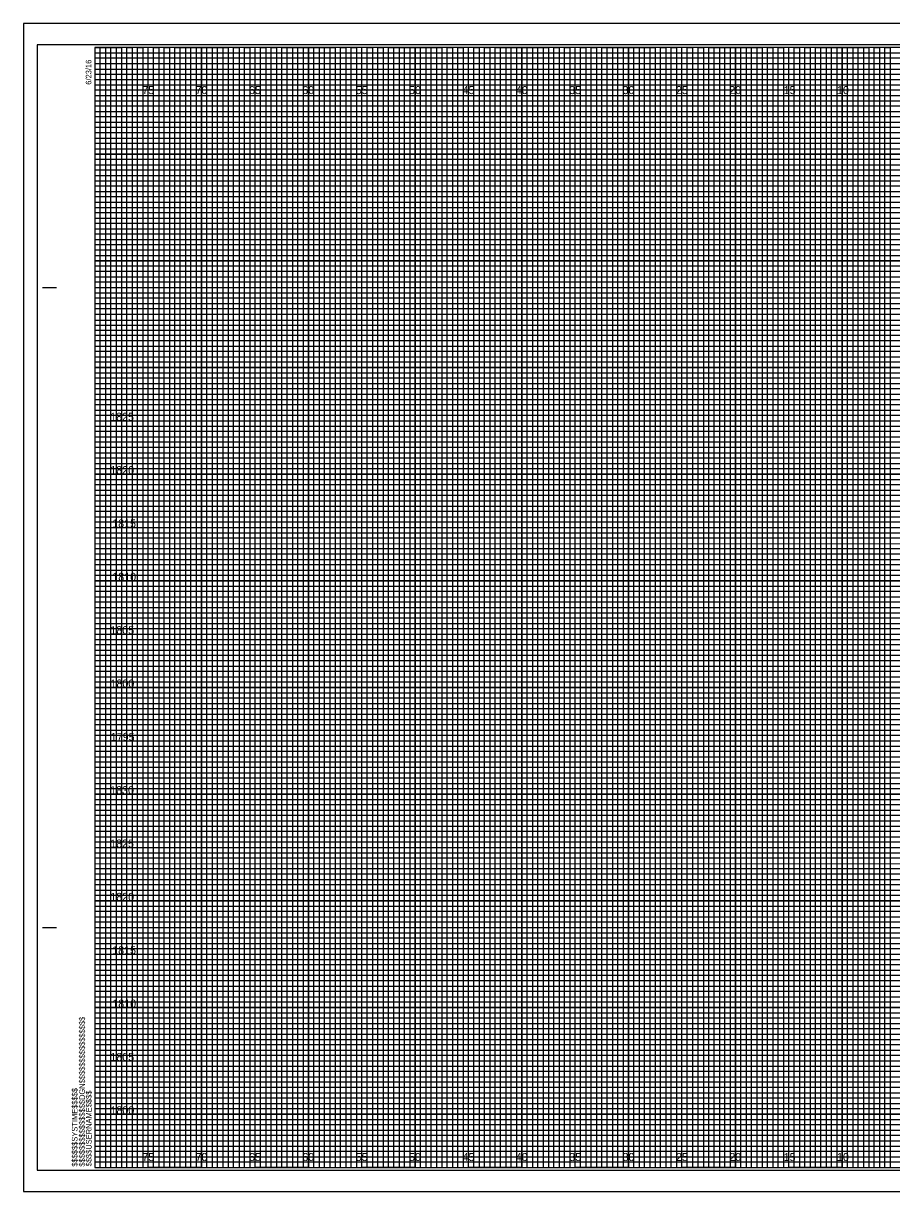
# Model space of a CAD drawing. Extents: x -7 to 162, y -2 to 767.
# Drawn here: x -6.7 to 74.6, y 217.7 to 327.2 of the extents above; entities that cross this region are included whole.
import ezdxf

# ---------------------------------------------------------------- set-up
doc = ezdxf.new("R2010")
doc.units = 0
for name, color, linetype in [('Prop Grid Mask', 7, 'Continuous'), ('Prop XS Elevation Labels', 7, 'Continuous'), ('Sheet Cross Section CELL', 7, 'Continuous'), ('Sheet Cross Section Grid Major CELL', 7, 'Continuous'), ('Sheet Cross Section Grid Middle CELL', 7, 'Continuous'), ('Sheet Cross Section Grid Minor 1 CELL', 7, 'Continuous'), ('Sheet Cross Section Grid Minor 2 CELL', 7, 'Continuous'), ('Sheet Cutting Line CELL', 7, 'Continuous'), ('Sheet DOT Grid CELL', 7, 'Continuous'), ('Sheet Plot Border Inside CELL', 7, 'Continuous'), ('Sheet Plot Border Outside CELL', 7, 'Continuous')]:
    doc.layers.add(name, color=color, linetype=linetype)

msp = doc.modelspace()

# ---------------------------------------------------------------- linework, layer by layer
at = {"layer": 'Sheet Cross Section CELL'}
for p, q in [((-4.9, 302.5), (-3.65, 302.5)), ((-4.85, 302.5), (-3.6, 302.5)), ((-4.9, 242.5), (-3.65, 242.5)), ((-4.85, 242.5), (-3.6, 242.5)), ((0, 220), (0, 220)), ((0, 220), (0, 220)), ((0, 220), (0, 220)), ((0, 220), (0, 220)), ((0, 220), (0, 220)), ((0, 220), (0, 220)), ((0, 220), (0, 220))]:
    msp.add_line(p, q, dxfattribs=at)
msp.add_lwpolyline([(160, 325), (0, 325), (0, 220), (160, 220)], close=True, dxfattribs=at)
at = {"layer": 'Sheet Cross Section Grid Major CELL'}
for p, q in [((5, 325), (0, 325)), ((5, 220), (5, 325)), ((15, 325), (10, 325)), ((10, 325), (10, 220)), ((15, 220), (15, 325)), ((25, 325), (20, 325)), ((20, 325), (20, 220)), ((25, 220), (25, 325)), ((35, 325), (30, 325)), ((30, 325), (30, 220)), ((35, 220), (35, 325)), ((45, 325), (40, 325)), ((40, 325), (40, 220)), ((45, 220), (45, 325)), ((55, 325), (50, 325)), ((50, 325), (50, 220)), ((55, 220), (55, 325)), ((65, 325), (60, 325)), ((60, 325), (60, 220)), ((65, 220), (65, 325)), ((75, 325), (70, 325)), ((70, 325), (70, 220)), ((10, 220), (5, 220)), ((20, 220), (15, 220)), ((30, 220), (25, 220)), ((40, 220), (35, 220)), ((50, 220), (45, 220)), ((60, 220), (55, 220)), ((70, 220), (65, 220))]:
    msp.add_line(p, q, dxfattribs=at)
for points in [[(0, 320), (160, 320), (160, 315), (0, 315)], [(0, 310), (160, 310), (160, 305), (0, 305)], [(0, 300), (160, 300), (160, 295), (0, 295)], [(0, 290), (160, 290), (160, 285), (0, 285)], [(0, 280), (160, 280), (160, 275), (0, 275)], [(0, 270), (160, 270), (160, 265), (0, 265)], [(0, 260), (160, 260), (160, 255), (0, 255)], [(0, 250), (160, 250), (160, 245), (0, 245)], [(0, 240), (160, 240), (160, 235), (0, 235)], [(0, 230), (160, 230), (160, 225), (0, 225)]]:
    msp.add_lwpolyline(points, dxfattribs=at)
at = {"layer": 'Sheet Cross Section Grid Middle CELL'}
for points in [[(0, 325), (2.5, 325), (2.5, 220), (7.5, 220), (7.5, 325), (12.5, 325), (12.5, 220), (17.5, 220), (17.5, 325), (22.5, 325), (22.5, 220), (27.5, 220), (27.5, 325), (32.5, 325), (32.5, 220), (37.5, 220), (37.5, 325), (42.5, 325), (42.5, 220), (47.5, 220), (47.5, 325), (52.5, 325), (52.5, 220), (57.5, 220), (57.5, 325), (62.5, 325), (62.5, 220), (67.5, 220), (67.5, 325), (72.5, 325), (72.5, 220), (77.5, 220)], [(0, 322.5), (137.5, 322.5)], [(0, 312.5), (160, 312.5), (160, 317.5), (0, 317.5)], [(0, 302.5), (160, 302.5), (160, 307.5), (0, 307.5)], [(0, 292.5), (160, 292.5), (160, 297.5), (0, 297.5)], [(0, 282.5), (160, 282.5), (160, 287.5), (0, 287.5)], [(0, 272.5), (160, 272.5), (160, 277.5), (0, 277.5)], [(0, 262.5), (160, 262.5), (160, 267.5), (0, 267.5)], [(0, 252.5), (160, 252.5), (160, 257.5), (0, 257.5)], [(0, 242.5), (160, 242.5), (160, 247.5), (0, 247.5)], [(0, 232.5), (160, 232.5), (160, 237.5), (0, 237.5)], [(0, 222.5), (160, 222.5), (160, 227.5), (0, 227.5)]]:
    msp.add_lwpolyline(points, dxfattribs=at)
at = {"layer": 'Sheet Cross Section Grid Minor 1 CELL'}
for p, q in [((0, 324.5), (130, 324.5)), ((130, 323.99), (0, 323.99)), ((0, 323.99), (0, 323.5)), ((0, 323.5), (130, 323.5)), ((130, 322.94), (0, 322.94)), ((0, 322.94), (0, 322)), ((0, 322), (160, 322))]:
    msp.add_line(p, q, dxfattribs=at)
for points in [[(0, 321.5), (135, 321.5), (160, 321.5), (160, 321), (0, 321)], [(0, 320.5), (160, 320.5), (160, 319.5), (0, 319.5)], [(0, 319), (160, 319), (160, 318.5), (0, 318.49)], [(0, 318), (160, 318), (160, 317), (0, 317)], [(0, 316.5), (160, 316.5), (160, 316), (0, 316)], [(0, 315.5), (160, 315.5), (160, 314.5), (0, 314.5)], [(0, 314), (160, 314), (160, 313.5), (0, 313.5)], [(0, 313), (160, 313), (160, 312), (0, 312)], [(0, 311.5), (160, 311.5), (160, 311), (0, 311)], [(0, 310.5), (160, 310.5), (160, 309.5), (0, 309.5)], [(0, 309), (160, 309), (160, 308.5), (0, 308.5)], [(0, 308), (160, 308), (160, 306.98), (160, 306.5), (160, 306), (0, 306)], [(0, 307), (160, 307), (160, 306.5), (0, 306.5)], [(0, 305.5), (160, 305.5), (160, 304.5), (0, 304.51)], [(0, 304.51), (160, 304.5), (160, 304), (0, 304)], [(0, 303.5), (160, 303.5), (160, 303), (0, 303)], [(0, 302), (160, 302), (160, 301.5), (0, 301.5)], [(0, 301), (160, 301), (160, 300.5), (0, 300.5)], [(-0.04, 299.44), (160, 299.44), (160, 298.94), (-0.04, 298.94)], [(0, 298.5), (160, 298.5), (160, 298), (0, 298)], [(0, 297), (160, 297), (160, 296.5), (0, 296.5)], [(0, 296), (160, 296), (160, 295.5), (0, 295.5)], [(0, 294.5), (160, 294.5), (160, 294), (0, 294)], [(0, 293.5), (160, 293.5), (160, 293), (0, 293)], [(0, 292), (160, 292), (160, 291.5), (0, 291.5)], [(0, 291), (160, 291), (160, 290.5), (0, 290.5)], [(0, 289.5), (160, 289.5), (160, 288.99), (0, 289)], [(0, 288.5), (160, 288.5), (160, 288), (0, 288)], [(0, 287), (160, 287), (160, 286.5), (0, 286.5)], [(0, 286), (160, 286), (160, 285.5), (0, 285.5)], [(0, 284.5), (160, 284.5), (160, 284), (0, 284)], [(0, 283.5), (160, 283.5), (160, 283), (0, 283)], [(0, 282), (160, 282), (160, 281.5), (0, 281.5)], [(0, 281), (160, 281), (160, 280.5), (0, 280.5)], [(0, 279.5), (160, 279.5), (160, 279), (0, 279)], [(0, 278.5), (160.03, 278.45), (160, 278), (0, 278)], [(0, 277), (160, 277), (160, 276.5), (0, 276.5)], [(0, 276), (160, 276), (160, 275.5), (0, 275.5)], [(0, 274.5), (160, 274.5), (160, 274), (0, 274)], [(0, 273.5), (160, 273.5), (160, 273), (0, 273)], [(0, 272), (160, 272), (160, 271.5), (0, 271.5)], [(0, 271), (160, 271), (160, 270.5), (0, 270.5)], [(0, 269.5), (160, 269.5), (160, 269), (0, 269)], [(0, 268.5), (160, 268.5), (160, 268), (0, 268)], [(0, 267), (160, 267), (160, 266.5), (0, 266.5)], [(0, 266), (160, 266), (160, 265.5), (0, 265.5)], [(0, 264.5), (160, 264.5), (160, 264), (0, 264)], [(0, 263.5), (160, 263.5), (160, 263), (0, 263)], [(0, 262), (160, 262), (160, 261.5), (0, 261.5)], [(0, 261), (160, 261), (160, 260.5), (0, 260.5)], [(0, 259.5), (160, 259.5), (160, 258.99), (0, 259)], [(0, 258.5), (160, 258.5), (160, 258), (0, 258)], [(0, 257), (160, 257), (160, 256.5), (0, 256.5)], [(0, 256), (160, 256), (160, 255.5), (0, 255.5)], [(0, 254.5), (160, 254.5), (160, 254), (0, 254)], [(0, 253.5), (160, 253.5), (160, 253), (0, 253)], [(0, 252), (160, 252), (160, 251.5), (0, 251.5)], [(0, 251), (160, 251), (160, 250.5), (0, 250.5)], [(0, 249.5), (160, 249.5), (160, 249), (0, 249)], [(0, 248.5), (160.03, 248.46), (160, 248), (0, 248)], [(0, 247), (160, 247), (160, 246.5), (0, 246.5)], [(0, 246), (160, 246), (160, 245.5), (0, 245.5)], [(0, 244.5), (160, 244.5), (160, 244), (0, 244)], [(0, 243.5), (160, 243.5), (160, 243), (0, 243)], [(0, 242), (160, 242), (160, 241.5), (0, 241.5)], [(0, 241), (160, 241), (160, 240.5), (0, 240.5)], [(0, 239.5), (160, 239.5), (160, 239), (0, 239)], [(0, 238.5), (160, 238.5), (160, 238), (0, 238)], [(0, 237), (160, 237), (160, 236.5), (0, 236.5)], [(0, 236), (160, 236), (160, 235.5), (0, 235.5)], [(0, 234.5), (160, 234.5), (160, 234), (0, 234)], [(0, 233.5), (160, 233.5), (160, 233), (0, 233)], [(0, 232), (160, 232), (160, 231.5), (0, 231.5)], [(0, 231), (160, 231), (160, 230.5), (0, 230.5)], [(0, 229.5), (160, 229.5), (160, 229), (0, 229)], [(0, 228.5), (160, 228.5), (160, 228), (0, 228)], [(0, 227), (160, 227), (160, 226.5), (0, 226.5)], [(0, 226), (160, 226), (160, 225.5), (0, 225.5)], [(0, 224.5), (160, 224.5), (160, 224), (0, 224)], [(0, 223.5), (160, 223.5), (160, 223), (0, 223)], [(0, 222), (160, 222), (160, 221.5), (0, 221.5)], [(0, 221), (160, 221), (160, 220.5), (0, 220.5)]]:
    msp.add_lwpolyline(points, dxfattribs=at)
at = {"layer": 'Sheet Cross Section Grid Minor 2 CELL'}
for points in [[(0, 220), (0.5, 220), (0.5, 325), (1, 325), (1, 220)], [(1, 220), (1.5, 220), (1.5, 325), (2, 325), (2, 220)], [(2.5, 220), (3, 220), (3, 325), (3.5, 325), (3.5, 220)], [(3.5, 220), (4, 220), (4, 325), (4.5, 325), (4.5, 220)], [(5, 220), (5.5, 220), (5.5, 325), (6, 325), (6, 220)], [(6, 220), (6.5, 220), (6.5, 325), (7, 325), (7, 220)], [(7.5, 220), (8, 220), (8, 325), (8.5, 325), (8.5, 220)], [(8.5, 220), (9, 220), (9, 325), (9.5, 325), (9.5, 220)], [(10, 220), (10.5, 220), (10.5, 325), (11, 325), (11, 220)], [(11, 220), (11.5, 220), (11.5, 325), (12, 325), (12, 220)], [(12.5, 220), (13, 220), (13, 325), (13.5, 325), (13.5, 220)], [(13.5, 220), (14, 220), (14, 325), (14.5, 325), (14.5, 220)], [(15, 220), (15.5, 220), (15.5, 325), (16, 325), (16, 220)], [(16, 220), (16.5, 220), (16.5, 325), (17, 325), (17, 220)], [(17.5, 220), (18, 220), (18, 325), (18.5, 325), (18.5, 220)], [(18.5, 220), (19, 220), (19, 325), (19.5, 325), (19.5, 220)], [(20, 220), (20.5, 220), (20.5, 325), (21, 325), (21, 220)], [(21, 220), (21.5, 220), (21.5, 325), (22, 325), (22, 220)], [(22.5, 220), (23, 220), (23, 325), (23.5, 325), (23.5, 220)], [(23.5, 220), (24, 220), (24, 325), (24.5, 325), (24.5, 220)], [(25, 220), (25.5, 220), (25.5, 325), (26, 325), (26, 220)], [(26, 220), (26.5, 220), (26.5, 325), (27, 325), (27, 220)], [(27.5, 220), (28, 220), (28, 325), (28.5, 325), (28.5, 220)], [(28.5, 220), (29, 220), (29, 325), (29.5, 325), (29.5, 220)], [(30, 220), (30.5, 220), (30.5, 325), (31, 325), (31, 220)], [(31, 220), (31.5, 220), (31.5, 325), (32, 325), (32, 220)], [(32.5, 220), (33, 220), (33, 325), (33.5, 325), (33.5, 220)], [(33.5, 220), (34, 220), (34, 325), (34.5, 325), (34.5, 220)], [(35, 220), (35.5, 220), (35.5, 325), (36, 325), (36, 220)], [(36, 220), (36.5, 220), (36.5, 325), (37, 325), (37, 220)], [(37.5, 220), (38, 220), (38, 325), (38.5, 325), (38.5, 220)], [(38.5, 220), (39, 220), (39, 325), (39.5, 325), (39.5, 220)], [(40, 220), (40.5, 220), (40.5, 325), (41, 325), (41, 220)], [(41, 220), (41.5, 220), (41.5, 325), (42, 325), (42, 220)], [(42.5, 220), (43, 220), (43, 325), (43.5, 325), (43.5, 220)], [(43.5, 220), (44, 220), (44, 325), (44.5, 325), (44.5, 220)], [(45, 220), (45.5, 220), (45.5, 325), (46, 325), (46, 220)], [(46, 220), (46.5, 220), (46.5, 325), (47, 325), (47, 220)], [(47.5, 220), (48, 220), (48, 325), (48.5, 325), (48.5, 220)], [(48.5, 220), (49, 220), (49, 325), (49.5, 325), (49.5, 220)], [(50, 220), (50.5, 220), (50.5, 325), (51, 325), (51, 220)], [(51, 220), (51.5, 220), (51.5, 325), (52, 325), (52, 220)], [(52.5, 220), (53, 220), (53, 325), (53.5, 325), (53.5, 220)], [(53.5, 220), (54, 220), (54, 325), (54.5, 325), (54.5, 220)], [(55, 220), (55.5, 220), (55.5, 325), (56, 325), (56, 220)], [(56, 220), (56.5, 220), (56.5, 325), (57, 325), (57, 220)], [(57.5, 220), (58, 220), (58, 325), (58.5, 325), (58.5, 220)], [(58.5, 220), (59, 220), (59, 325), (59.5, 325), (59.5, 220)], [(60, 220), (60.5, 220), (60.5, 325), (61, 325), (61, 220)], [(61, 220), (61.5, 220), (61.5, 325), (62, 325), (62, 220)], [(62.5, 220), (63, 220), (63, 325), (63.5, 325), (63.5, 220)], [(63.5, 220), (64, 220), (64, 325), (64.5, 325), (64.5, 220)], [(65, 220), (65.5, 220), (65.5, 325), (66, 325), (66, 220)], [(66, 220), (66.5, 220), (66.5, 325), (67, 325), (67, 220)], [(67.5, 220), (68, 220), (68, 325), (68.5, 325), (68.5, 220)], [(68.5, 220), (69, 220), (69, 325), (69.5, 325), (69.5, 220)], [(70, 220), (70.5, 220), (70.5, 325), (71, 325), (71, 220)], [(71, 220), (71.5, 220), (71.5, 325), (72, 325), (72, 220)], [(72.5, 220), (73, 220), (73, 325), (73.5, 325), (73.5, 220)], [(73.5, 220), (74, 220), (74, 325), (74.5, 325), (74.5, 220)]]:
    msp.add_lwpolyline(points, dxfattribs=at)
at = {"layer": 'Sheet Cutting Line CELL'}
for p, q in [((161.65, 327.25), (-6.7, 327.25)), ((-6.7, 327.25), (-6.7, 217.75)), ((-6.7, 217.75), (161.65, 217.75))]:
    msp.add_line(p, q, dxfattribs=at)
at = {"layer": 'Sheet DOT Grid CELL'}
for p, q in [((5, 220), (5, 325)), ((10, 220), (10, 325)), ((15, 220), (15, 325)), ((20, 220), (20, 325)), ((25, 220), (25, 325)), ((30, 220), (30, 325)), ((35, 220), (35, 325)), ((40, 220), (40, 325)), ((45, 220), (45, 325)), ((50, 220), (50, 325)), ((55, 220), (55, 325)), ((60, 220), (60, 325)), ((65, 220), (65, 325)), ((70, 220), (70, 325)), ((0, 320), (160, 320)), ((0, 315), (160, 315)), ((0, 310), (160, 310)), ((0, 305), (160, 305)), ((0, 300), (160, 300)), ((0, 295), (160, 295)), ((0, 290), (160, 290)), ((0, 285), (160, 285)), ((0, 280), (160, 280)), ((0, 275), (160, 275)), ((0, 270), (160, 270)), ((0, 265), (160, 265)), ((0, 260), (160, 260)), ((0, 255), (160, 255)), ((0, 250), (160, 250)), ((0, 245), (160, 245)), ((0, 240), (160, 240)), ((0, 235), (160, 235)), ((0, 230), (160, 230)), ((0, 225), (160, 225))]:
    msp.add_line(p, q, dxfattribs=at)
at = {"layer": 'Sheet Plot Border Inside CELL'}
msp.add_lwpolyline([(-5.4, 219.75), (161.2, 219.75), (161.2, 325.25), (-5.4, 325.25)], close=True, dxfattribs=at)
at = {"layer": 'Sheet Plot Border Outside CELL'}
msp.add_lwpolyline([(-6.7, 217.75), (161.65, 217.75), (161.65, 327.25), (-6.7, 327.25)], close=True, dxfattribs=at)

# ---------------------------------------------------------------- texts
at = {"layer": 'Prop Grid Mask'}
for s, p in [('75', (4.44, 320.62)), ('70', (9.43, 320.62)), ('65', (14.44, 320.62)), ('60', (19.43, 320.62)), ('55', (24.44, 320.62)), ('50', (29.43, 320.62)), ('45', (34.44, 320.62)), ('40', (39.43, 320.62)), ('35', (44.44, 320.62)), ('30', (49.43, 320.62)), ('25', (54.44, 320.62)), ('20', (59.43, 320.62)), ('15', (64.53, 320.62)), ('10', (69.52, 320.62)), ('75', (4.44, 220.62)), ('70', (9.43, 220.62)), ('65', (14.44, 220.62)), ('60', (19.43, 220.62)), ('55', (24.44, 220.62)), ('50', (29.43, 220.62)), ('45', (34.44, 220.62)), ('40', (39.43, 220.62)), ('35', (44.44, 220.62)), ('30', (49.43, 220.62)), ('25', (54.44, 220.62)), ('20', (59.43, 220.62)), ('15', (64.53, 220.62)), ('10', (69.52, 220.62))]:
    msp.add_text(s, height=0.75, dxfattribs=at).set_placement(p)
at = {"layer": 'Prop XS Elevation Labels'}
for s, p in [('1825', (1.43, 290)), ('1820', (1.44, 285)), ('1815', (1.62, 280)), ('1810', (1.63, 275)), ('1805', (1.45, 270)), ('1800', (1.46, 265)), ('1795', (1.49, 260)), ('1830', (1.43, 255)), ('1825', (1.43, 250)), ('1820', (1.44, 245)), ('1815', (1.62, 240)), ('1810', (1.63, 235)), ('1805', (1.45, 230)), ('1800', (1.46, 225))]:
    msp.add_text(s, height=0.75, dxfattribs=at).set_placement(p)
at = {"layer": 'Sheet Cross Section CELL'}
for s, p in [('6/23/16', (-0.33, 321.5)), ('$$$$$$$$$$$$$$$$DGN$$$$$$$$$$$$$$$$', (-0.94, 220.09)), ('$$$$$$SYSTIME$$$$$', (-1.63, 220.09)), ('$$$$USERNAME$$$$', (-0.31, 220.12))]:
    msp.add_text(s, height=0.525, rotation=90, dxfattribs=at).set_placement(p)

doc.saveas('drawing.dxf')
